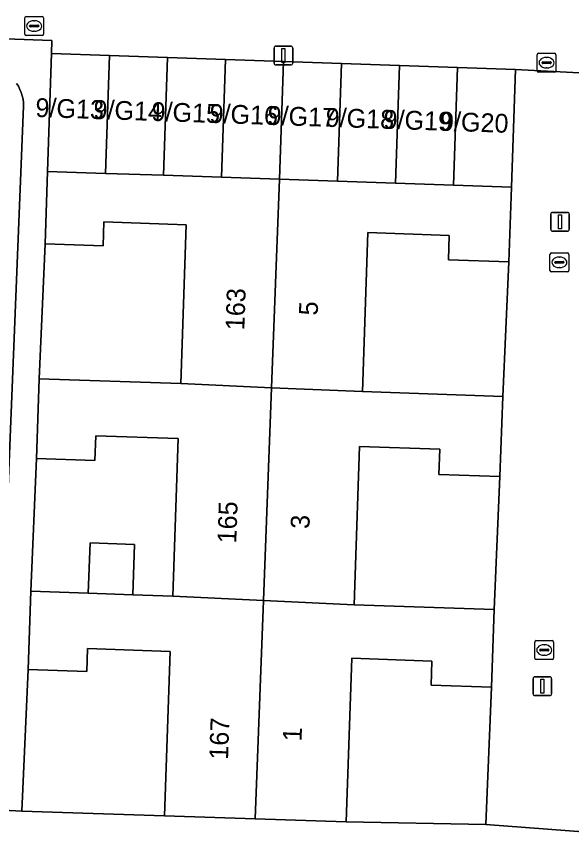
# Model space of a CAD drawing. Extents: x 160786 to 161429, y 386828 to 387485.
# Drawn here: x 160952.8 to 160982.31, y 387304.46 to 387348.56 of the extents above; entities that cross this region are included whole.
import ezdxf

# ---------------------------------------------------------------- set-up
doc = ezdxf.new("R2010")
doc.units = 0
for name, color, linetype in [('IMGEO_Brandkraan', 7, 'Continuous'), ('IMGEO_Erf', 7, 'Continuous'), ('IMGEO_Groenvoorziening', 7, 'Continuous'), ('IMGEO_Kolk', 7, 'Continuous'), ('IMGEO_Lichtmast', 7, 'Continuous'), ('IMGEO_Muur', 7, 'Continuous'), ('IMGEO_Pand', 7, 'Continuous'), ('IMGEO_Pand_nummerreeks', 7, 'Continuous'), ('IMGEO_Rijbaan_lokaal_open', 7, 'Continuous'), ('IMGEO_Voetpad_open', 7, 'Continuous')]:
    doc.layers.add(name, color=color, linetype=linetype)

msp = doc.modelspace()

# ---------------------------------------------------------------- linework, layer by layer
at = {"layer": 'IMGEO_Brandkraan'}
for p, q in [((160953.239, 387347.631), (160953.239, 387348.483)), ((160953.314, 387348.557), (160954.166, 387348.557)), ((160953.727, 387348.337), (160953.752, 387348.337)), ((160954.24, 387348.483), (160954.24, 387347.631)), ((160953.498, 387348.051), (160953.498, 387348.063)), ((160953.936, 387348.014), (160953.538, 387348.014)), ((160953.541, 387348.1), (160953.939, 387348.1)), ((160953.982, 387348.063), (160953.982, 387348.051)), ((160954.166, 387347.557), (160953.314, 387347.557)), ((160953.75, 387347.777), (160953.725, 387347.777)), ((160980.488, 387345.681), (160980.488, 387346.533)), ((160980.563, 387346.607), (160981.415, 387346.607)), ((160981.489, 387346.533), (160981.489, 387345.681)), ((160980.747, 387346.101), (160980.747, 387346.113)), ((160980.79, 387346.15), (160981.188, 387346.15)), ((160980.976, 387346.387), (160981.001, 387346.387)), ((160981.231, 387346.113), (160981.231, 387346.101)), ((160981.185, 387346.064), (160980.787, 387346.064)), ((160980.999, 387345.827), (160980.974, 387345.827)), ((160981.415, 387345.607), (160980.563, 387345.607))]:
    msp.add_line(p, q, dxfattribs=at)
for points in [[(160953.239, 387347.631), (160953.239, 387348.483)], [(160953.314, 387348.557), (160954.166, 387348.557)], [(160954.24, 387348.483), (160954.24, 387347.631)], [(160954.166, 387347.557), (160953.314, 387347.557)], [(160980.488, 387345.681), (160980.488, 387346.533)], [(160980.563, 387346.607), (160981.415, 387346.607)], [(160981.489, 387346.533), (160981.489, 387345.681)], [(160981.415, 387345.607), (160980.563, 387345.607)]]:
    msp.add_lwpolyline(points, dxfattribs=at)
for centre, radius, start, end in [((160953.316, 387348.481), 0.0765, 91.552, 178.448), ((160953.316, 387348.481), 0.0765, 91.552, 178.448), ((160954.164, 387348.481), 0.0765, 1.552, 88.448), ((160954.164, 387348.481), 0.0765, 1.552, 88.448), ((160953.538, 387348.06), 0.0403, 85.8775, 175.7526), ((160953.535, 387348.05), 0.0366, 178.938, 274.7102), ((160953.939, 387348.057), 0.043, 264.8664, 352.4533), ((160953.943, 387348.062), 0.0386, 1.7309, 96.639), ((160953.316, 387347.633), 0.0765, 181.552, 268.448), ((160953.316, 387347.633), 0.0765, 181.552, 268.448), ((160954.164, 387347.633), 0.0765, 271.552, 358.448), ((160954.164, 387347.633), 0.0765, 271.552, 358.448), ((160980.565, 387346.531), 0.0765, 91.552, 178.448), ((160980.565, 387346.531), 0.0765, 91.552, 178.448), ((160981.413, 387346.531), 0.0765, 1.552, 88.448), ((160981.413, 387346.531), 0.0765, 1.552, 88.448), ((160980.787, 387346.11), 0.0403, 85.8775, 175.7526), ((160980.784, 387346.1), 0.0366, 178.938, 274.7102), ((160981.188, 387346.107), 0.043, 264.8664, 352.4533), ((160981.192, 387346.112), 0.0386, 1.7309, 96.639), ((160980.565, 387345.683), 0.0765, 181.552, 268.448), ((160980.565, 387345.683), 0.0765, 181.552, 268.448), ((160981.413, 387345.683), 0.0765, 271.552, 358.448), ((160981.413, 387345.683), 0.0765, 271.552, 358.448)]:
    msp.add_arc(centre, radius, start, end, dxfattribs=at)
for centre, major_axis, ratio, start_param, end_param in [((160953.726, 387348.057), (-0.387, 0.002), 0.722429, 4.712389, 7.853982), ((160953.751, 387348.057), (-0.39, 0.002), 0.717154, 1.570796, 4.712389), ((160980.975, 387346.107), (-0.387, 0.002), 0.722429, 4.712389, 7.853982), ((160981, 387346.107), (-0.39, 0.002), 0.717154, 1.570796, 4.712389)]:
    msp.add_ellipse(centre, major_axis=major_axis, ratio=ratio, start_param=start_param, end_param=end_param, dxfattribs=at)
at = {"layer": 'IMGEO_Erf'}
for points in [[(160954.012, 387329.308), (160961.534, 387329.052), (160961.822, 387337.499), (160957.443, 387337.649), (160957.399, 387336.371), (160954.318, 387336.476)], [(160978.983, 387335.52), (160975.766, 387335.63), (160975.81, 387336.929), (160971.488, 387337.077), (160971.199, 387328.627), (160978.655, 387328.372)], [(160961.393, 387326.136), (160957.01, 387326.285), (160956.965, 387324.973), (160953.868, 387325.079), (160953.561, 387318.014), (160956.617, 387317.91), (160956.708, 387320.589), (160959.069, 387320.509), (160958.978, 387317.829), (160961.107, 387317.756)], [(160978.51, 387324.111), (160975.267, 387324.221), (160975.313, 387325.572), (160971.045, 387325.718), (160970.758, 387317.3), (160978.196, 387317.046)], [(160960.665, 387306.088), (160960.963, 387314.818), (160956.58, 387314.968), (160956.539, 387313.76), (160953.419, 387313.867), (160953.082, 387306.333)], [(160978.055, 387312.917), (160974.844, 387313.027), (160974.888, 387314.309), (160970.629, 387314.454), (160970.332, 387305.758), (160977.765, 387305.618)]]:
    msp.add_lwpolyline(points, close=True, dxfattribs=at)
at = {"layer": 'IMGEO_Groenvoorziening'}
msp.add_lwpolyline([(160951.739, 387308.588), (160953.174, 387343.794), (160953.168, 387343.979), (160953.146, 387344.162), (160953.107, 387344.343), (160953.052, 387344.519), (160952.982, 387344.69), (160952.897, 387344.854), (160952.797, 387345.01)], dxfattribs=at)
at = {"layer": 'IMGEO_Kolk'}
for p, q in [((160981.244, 387335.997), (160982.096, 387335.997)), ((160981.169, 387335.071), (160981.169, 387335.923)), ((160981.428, 387335.491), (160981.428, 387335.503)), ((160981.471, 387335.54), (160981.869, 387335.54)), ((160981.657, 387335.777), (160981.682, 387335.777)), ((160981.912, 387335.503), (160981.912, 387335.491)), ((160982.17, 387335.923), (160982.17, 387335.071)), ((160981.866, 387335.454), (160981.468, 387335.454)), ((160981.68, 387335.217), (160981.655, 387335.217)), ((160982.096, 387334.997), (160981.244, 387334.997)), ((160980.364, 387314.467), (160980.364, 387315.319)), ((160980.439, 387315.393), (160981.291, 387315.393)), ((160981.365, 387315.319), (160981.365, 387314.467)), ((160980.623, 387314.887), (160980.623, 387314.899)), ((160981.061, 387314.85), (160980.663, 387314.85)), ((160980.666, 387314.936), (160981.064, 387314.936)), ((160980.852, 387315.173), (160980.877, 387315.173)), ((160981.107, 387314.899), (160981.107, 387314.887)), ((160981.291, 387314.393), (160980.439, 387314.393)), ((160980.875, 387314.613), (160980.85, 387314.613))]:
    msp.add_line(p, q, dxfattribs=at)
for points in [[(160981.244, 387335.997), (160982.096, 387335.997)], [(160981.169, 387335.071), (160981.169, 387335.923)], [(160982.17, 387335.923), (160982.17, 387335.071)], [(160982.096, 387334.997), (160981.244, 387334.997)], [(160980.364, 387314.467), (160980.364, 387315.319)], [(160980.439, 387315.393), (160981.291, 387315.393)], [(160981.365, 387315.319), (160981.365, 387314.467)], [(160981.291, 387314.393), (160980.439, 387314.393)]]:
    msp.add_lwpolyline(points, dxfattribs=at)
for centre, radius, start, end in [((160981.246, 387335.921), 0.0765, 91.552, 178.448), ((160981.246, 387335.921), 0.0765, 91.552, 178.448), ((160982.094, 387335.921), 0.0765, 1.552, 88.448), ((160982.094, 387335.921), 0.0765, 1.552, 88.448), ((160981.468, 387335.5), 0.0403, 85.8775, 175.7526), ((160981.465, 387335.49), 0.0366, 178.938, 274.7102), ((160981.869, 387335.497), 0.043, 264.8664, 352.4533), ((160981.873, 387335.502), 0.0386, 1.7309, 96.639), ((160981.246, 387335.073), 0.0765, 181.552, 268.448), ((160981.246, 387335.073), 0.0765, 181.552, 268.448), ((160982.094, 387335.073), 0.0765, 271.552, 358.448), ((160982.094, 387335.073), 0.0765, 271.552, 358.448), ((160980.441, 387315.317), 0.0765, 91.552, 178.448), ((160980.441, 387315.317), 0.0765, 91.552, 178.448), ((160981.289, 387315.317), 0.0765, 1.552, 88.448), ((160981.289, 387315.317), 0.0765, 1.552, 88.448), ((160980.663, 387314.896), 0.0403, 85.8775, 175.7526), ((160980.66, 387314.886), 0.0366, 178.938, 274.7102), ((160981.064, 387314.893), 0.043, 264.8664, 352.4533), ((160981.068, 387314.898), 0.0386, 1.7309, 96.639), ((160980.441, 387314.469), 0.0765, 181.552, 268.448), ((160980.441, 387314.469), 0.0765, 181.552, 268.448), ((160981.289, 387314.469), 0.0765, 271.552, 358.448), ((160981.289, 387314.469), 0.0765, 271.552, 358.448)]:
    msp.add_arc(centre, radius, start, end, dxfattribs=at)
for centre, major_axis, ratio, start_param, end_param in [((160981.656, 387335.497), (-0.387, 0.002), 0.722429, 4.712389, 7.853982), ((160981.681, 387335.497), (-0.39, 0.002), 0.717154, 1.570796, 4.712389), ((160980.851, 387314.893), (-0.387, 0.002), 0.722429, 4.712389, 7.853982), ((160980.876, 387314.893), (-0.39, 0.002), 0.717154, 1.570796, 4.712389)]:
    msp.add_ellipse(centre, major_axis=major_axis, ratio=ratio, start_param=start_param, end_param=end_param, dxfattribs=at)
at = {"layer": 'IMGEO_Lichtmast'}
for p, q in [((160966.597, 387346.986), (160967.387, 387346.986)), ((160967.387, 387346.986), (160966.597, 387346.986)), ((160966.497, 387346.086), (160966.497, 387346.886)), ((160966.497, 387346.886), (160966.497, 387346.086)), ((160967.487, 387346.886), (160967.487, 387346.086)), ((160967.487, 387346.086), (160967.487, 387346.886)), ((160967.387, 387345.986), (160966.597, 387345.986)), ((160966.597, 387345.986), (160967.387, 387345.986)), ((160981.307, 387338.152), (160982.097, 387338.152)), ((160982.097, 387338.152), (160981.307, 387338.152)), ((160981.207, 387337.252), (160981.207, 387338.052)), ((160981.207, 387338.052), (160981.207, 387337.252)), ((160982.197, 387338.052), (160982.197, 387337.252)), ((160982.197, 387337.252), (160982.197, 387338.052)), ((160982.097, 387337.152), (160981.307, 387337.152)), ((160981.307, 387337.152), (160982.097, 387337.152)), ((160980.369, 387313.471), (160981.159, 387313.471)), ((160981.159, 387313.471), (160980.369, 387313.471)), ((160980.269, 387312.571), (160980.269, 387313.371)), ((160980.269, 387313.371), (160980.269, 387312.571)), ((160981.259, 387313.371), (160981.259, 387312.571)), ((160981.259, 387312.571), (160981.259, 387313.371)), ((160981.159, 387312.471), (160980.369, 387312.471)), ((160980.369, 387312.471), (160981.159, 387312.471))]:
    msp.add_line(p, q, dxfattribs=at)
for points in [[(160966.917, 387346.861), (160967.067, 387346.861), (160967.067, 387346.111), (160966.917, 387346.111), (160966.917, 387346.861)], [(160981.627, 387338.027), (160981.777, 387338.027), (160981.777, 387337.277), (160981.627, 387337.277), (160981.627, 387338.027)], [(160980.689, 387313.346), (160980.839, 387313.346), (160980.839, 387312.596), (160980.689, 387312.596), (160980.689, 387313.346)]]:
    msp.add_lwpolyline(points, dxfattribs=at)
for centre, start, end in [((160966.597, 387346.886), 90, 180), ((160966.597, 387346.886), 90, 180), ((160967.387, 387346.886), 0, 90), ((160967.387, 387346.886), 360, 90), ((160966.597, 387346.086), 180, 270), ((160966.597, 387346.086), 180, 270), ((160967.387, 387346.086), 270, 0), ((160967.387, 387346.086), 270, 0), ((160981.307, 387338.052), 90, 180), ((160981.307, 387338.052), 90, 180), ((160982.097, 387338.052), 0, 90), ((160982.097, 387338.052), 360, 90), ((160981.307, 387337.252), 180, 270), ((160981.307, 387337.252), 180, 270), ((160982.097, 387337.252), 270, 0), ((160982.097, 387337.252), 270, 0), ((160980.369, 387313.371), 90, 180), ((160980.369, 387313.371), 90, 180), ((160981.159, 387313.371), 0, 90), ((160981.159, 387313.371), 360, 90), ((160980.369, 387312.571), 180, 270), ((160980.369, 387312.571), 180, 270), ((160981.159, 387312.571), 270, 0), ((160981.159, 387312.571), 270, 0)]:
    msp.add_arc(centre, 0.1, start, end, dxfattribs=at)
at = {"layer": 'IMGEO_Muur'}
for points in [[(160954.318, 387336.476), (160954.012, 387329.308)], [(160978.655, 387328.372), (160978.983, 387335.52)], [(160953.868, 387325.079), (160953.561, 387318.014)], [(160978.196, 387317.046), (160978.51, 387324.111)], [(160953.419, 387313.867), (160953.082, 387306.333)], [(160970.332, 387305.758), (160977.765, 387305.618), (160978.055, 387312.917)], [(160953.082, 387306.333), (160960.665, 387306.088)]]:
    msp.add_lwpolyline(points, dxfattribs=at)
at = {"layer": 'IMGEO_Pand'}
for points in [[(160954.663, 387346.596), (160954.449, 387340.332), (160957.533, 387340.227), (160957.747, 387346.491)], [(160960.83, 387346.386), (160957.747, 387346.491), (160957.533, 387340.227), (160960.617, 387340.122)], [(160960.617, 387340.122), (160963.7, 387340.017), (160963.914, 387346.28), (160960.83, 387346.386)], [(160966.998, 387346.175), (160963.914, 387346.28), (160963.7, 387340.017), (160966.788, 387339.912)], [(160966.788, 387339.912), (160969.868, 387339.807), (160970.082, 387346.07), (160966.998, 387346.175)], [(160973.166, 387345.964), (160970.082, 387346.07), (160969.868, 387339.807), (160972.952, 387339.702)], [(160976.249, 387345.859), (160973.166, 387345.964), (160972.952, 387339.702), (160976.036, 387339.597)], [(160979.333, 387345.754), (160976.249, 387345.859), (160976.036, 387339.597), (160979.119, 387339.492)], [(160954.318, 387336.476), (160957.399, 387336.371), (160957.443, 387337.649), (160961.822, 387337.499), (160961.534, 387329.052), (160966.368, 387328.837), (160966.788, 387339.912), (160963.7, 387340.017), (160960.617, 387340.122), (160957.533, 387340.227), (160954.449, 387340.332)], [(160979.119, 387339.492), (160976.036, 387339.597), (160972.952, 387339.702), (160969.868, 387339.807), (160966.788, 387339.912), (160966.368, 387328.837), (160971.199, 387328.627), (160971.488, 387337.077), (160975.81, 387336.929), (160975.766, 387335.63), (160978.983, 387335.52)], [(160953.868, 387325.079), (160956.965, 387324.973), (160957.01, 387326.285), (160961.393, 387326.136), (160961.107, 387317.756), (160965.938, 387317.527), (160966.368, 387328.837), (160961.534, 387329.052), (160954.012, 387329.308)], [(160978.655, 387328.372), (160971.199, 387328.627), (160966.368, 387328.837), (160965.938, 387317.527), (160970.758, 387317.3), (160971.045, 387325.718), (160975.313, 387325.572), (160975.267, 387324.221), (160978.51, 387324.111)], [(160956.617, 387317.91), (160958.978, 387317.829), (160959.069, 387320.509), (160956.708, 387320.589)], [(160965.938, 387317.527), (160961.107, 387317.756), (160958.978, 387317.829), (160956.617, 387317.91), (160953.561, 387318.014), (160953.419, 387313.867), (160956.539, 387313.76), (160956.58, 387314.968), (160960.963, 387314.818), (160960.665, 387306.088), (160965.498, 387305.923)], [(160978.196, 387317.046), (160970.758, 387317.3), (160965.938, 387317.527), (160965.498, 387305.923), (160970.332, 387305.758), (160970.629, 387314.454), (160974.888, 387314.309), (160974.844, 387313.027), (160978.055, 387312.917)]]:
    msp.add_lwpolyline(points, close=True, dxfattribs=at)
at = {"layer": 'IMGEO_Rijbaan_lokaal_open'}
msp.add_lwpolyline([(160943.825, 387347.669), (160954.685, 387347.288), (160954.663, 387346.596), (160957.747, 387346.491), (160960.83, 387346.386), (160963.914, 387346.28), (160966.998, 387346.175), (160970.082, 387346.07), (160973.166, 387345.964), (160976.249, 387345.859), (160979.333, 387345.754), (160984.758, 387345.458)], dxfattribs=at)
at = {"layer": 'IMGEO_Voetpad_open'}
for points in [[(160953.868, 387325.079), (160954.012, 387329.308), (160954.318, 387336.476), (160954.449, 387340.332), (160954.663, 387346.596), (160954.685, 387347.288), (160943.825, 387347.669)], [(160952.797, 387345.01), (160952.897, 387344.854), (160952.982, 387344.69), (160953.052, 387344.519), (160953.107, 387344.343), (160953.146, 387344.162), (160953.168, 387343.979), (160953.174, 387343.794), (160951.739, 387308.588)], [(160949.797, 387306.515), (160953.082, 387306.333), (160953.419, 387313.867), (160953.561, 387318.014), (160953.868, 387325.079)], [(161030.392, 387303.382), (161025.572, 387303.577), (161020.754, 387303.772), (161013.104, 387303.992), (161007.761, 387304.145), (161000.326, 387304.564), (161000, 387304.577), (160995.34, 387304.76), (160990.678, 387304.943), (160983.144, 387305.21), (160977.765, 387305.618), (160970.332, 387305.758), (160965.498, 387305.923), (160960.665, 387306.088), (160953.082, 387306.333), (160949.797, 387306.515), (160949.619, 387306.518), (160946.741, 387306.626), (160943.863, 387306.734)]]:
    msp.add_lwpolyline(points, dxfattribs=at)
msp.add_lwpolyline([(160984.055, 387328.17), (160984.36, 387335.313), (160984.508, 387339.08), (160984.758, 387345.458), (160979.333, 387345.754), (160979.119, 387339.492), (160978.983, 387335.52), (160978.655, 387328.372), (160978.51, 387324.111), (160978.196, 387317.046), (160978.055, 387312.917), (160977.765, 387305.618), (160983.144, 387305.21), (160983.467, 387312.699), (160983.626, 387316.762), (160983.887, 387323.905)], close=True, dxfattribs=at)

# ---------------------------------------------------------------- texts
at = {"layer": 'IMGEO_Pand_nummerreeks'}
for s, rotation, p in [('9/G13', 358.0667, (160953.793, 387343.227)), ('9/G14', 358.0667, (160956.879, 387343.123)), ('9/G15', 358.0667, (160959.965, 387343.018)), ('9/G16', 358.0667, (160963.051, 387342.914)), ('9/G17', 358.0667, (160966.137, 387342.81)), ('9/G18', 358.0667, (160969.226, 387342.706)), ('9/G19', 358.0667, (160972.305, 387342.602)), ('9/G20', 358.0667, (160975.306, 387342.501)), ('163', 88.0473, (160964.912, 387331.878)), ('5', 88.0412, (160968.816, 387332.662)), ('165', 88.0453, (160964.484, 387320.548)), ('3', 88.0473, (160968.374, 387321.319)), ('167', 88.0464, (160964.048, 387309.054)), ('1', 88.0439, (160967.957, 387310.03))]:
    msp.add_text(s, height=1, rotation=rotation, dxfattribs=at).set_placement(p)

doc.saveas('drawing.dxf')
